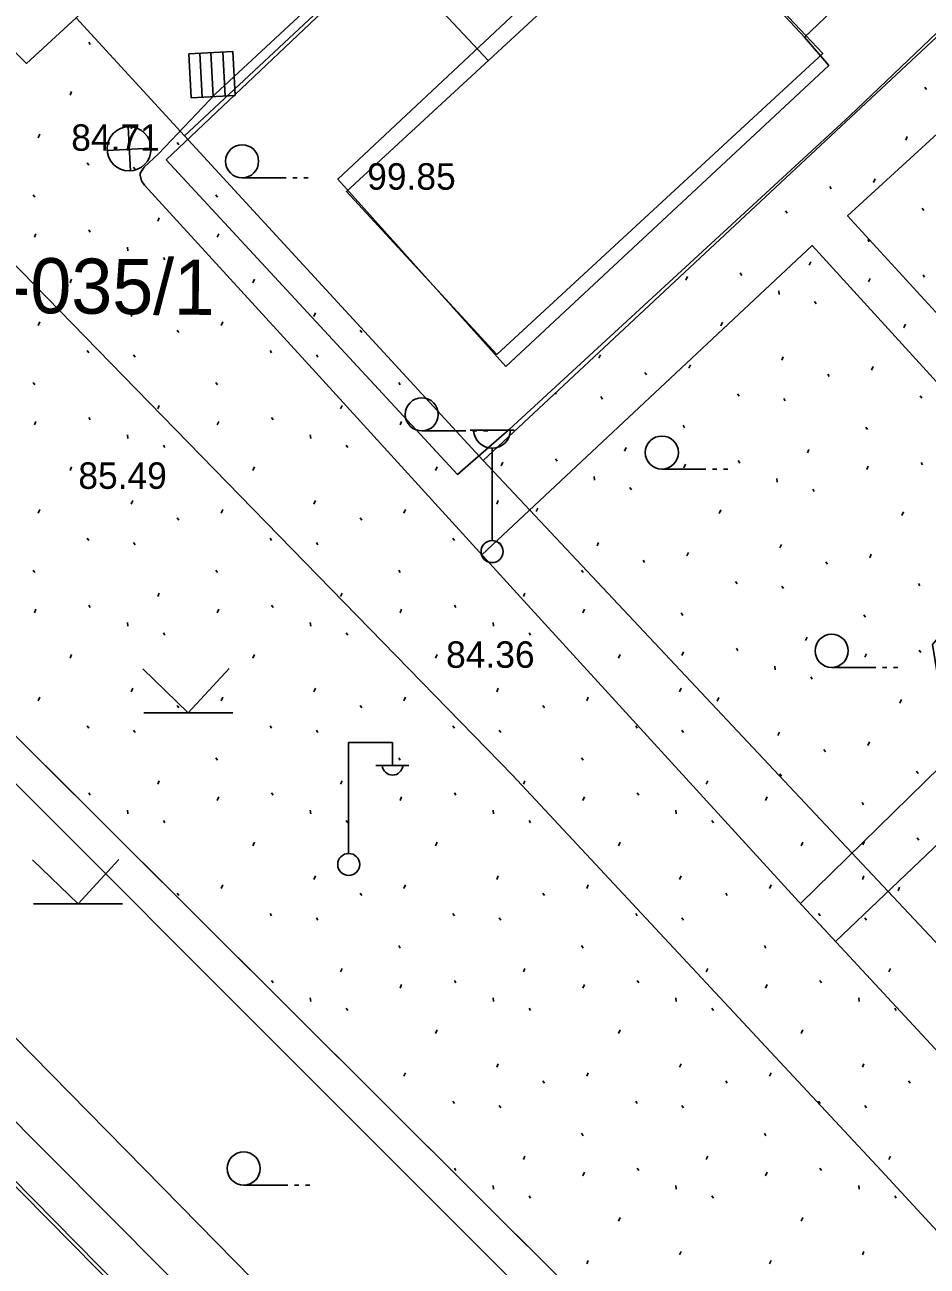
# Model space of a CAD drawing. Extents: x 412225 to 413380, y 4456471 to 4457189.
# Drawn here: x 412367.3 to 412408.2, y 4457046.4 to 4457102.7 of the extents above; entities that cross this region are included whole.
import ezdxf

# ---------------------------------------------------------------- set-up
doc = ezdxf.new("R2010")
doc.units = 0
for name, color, linetype in [('0_HALİHAZIR', 7, 'Continuous'), ('0_KADASTRO', 7, 'Continuous'), ('Level 27', 7, 'Continuous'), ('Level 41', 7, 'Continuous'), ('Level 56', 7, 'Continuous'), ('Level 57', 7, 'Continuous'), ('Level 59', 7, 'Continuous'), ('Level 62', 7, 'Continuous'), ('Level 8', 7, 'Continuous')]:
    doc.layers.add(name, color=color, linetype=linetype)

msp = doc.modelspace()

# ---------------------------------------------------------------- linework, layer by layer
at = {"layer": '0_HALİHAZIR'}
for p, q in [((412376.715, 4457101.483), (412374.717, 4457101.377)), ((412376.715, 4457101.483), (412374.717, 4457101.377)), ((412374.717, 4457101.377), (412374.823, 4457099.38)), ((412374.717, 4457101.377), (412374.823, 4457099.38)), ((412375.327, 4457099.406), (412375.221, 4457101.404)), ((412375.822, 4457099.433), (412375.716, 4457101.43)), ((412376.369, 4457099.461), (412376.263, 4457101.459)), ((412376.82, 4457099.485), (412376.715, 4457101.483)), ((412376.82, 4457099.485), (412376.715, 4457101.483)), ((412374.823, 4457099.38), (412376.82, 4457099.485)), ((412374.823, 4457099.38), (412376.82, 4457099.485)), ((412372.081, 4457096.06), (412371.976, 4457098.058)), ((412371.011, 4457096.995), (412373.008, 4457097.101)), ((412377.141, 4457095.752), (412379.141, 4457095.752)), ((412379.441, 4457095.752), (412379.641, 4457095.752)), ((412379.941, 4457095.752), (412380.141, 4457095.752)), ((412385.291, 4457084.277), (412387.291, 4457084.277)), ((412387.481, 4457084.305), (412389.481, 4457084.305)), ((412387.591, 4457084.277), (412387.791, 4457084.277)), ((412388.091, 4457084.277), (412388.291, 4457084.277)), ((412388.481, 4457079.305), (412388.481, 4457083.498)), ((412396.182, 4457082.545), (412398.182, 4457082.546)), ((412398.482, 4457082.546), (412398.682, 4457082.546)), ((412398.982, 4457082.546), (412399.182, 4457082.546)), ((412374.697, 4457071.497), (412372.637, 4457073.487)), ((412374.697, 4457071.497), (412376.547, 4457073.507)), ((412403.885, 4457073.554), (412405.886, 4457073.554)), ((412406.186, 4457073.554), (412406.386, 4457073.554)), ((412406.686, 4457073.554), (412406.886, 4457073.554)), ((412372.677, 4457071.497), (412376.717, 4457071.497)), ((412381.968, 4457065.141), (412381.968, 4457070.141)), ((412381.968, 4457070.141), (412383.968, 4457070.141)), ((412383.968, 4457069.141), (412383.968, 4457070.141)), ((412383.208, 4457069.101), (412384.708, 4457069.101)), ((412369.697, 4457062.837), (412367.637, 4457064.827)), ((412369.697, 4457062.837), (412371.547, 4457064.847)), ((412367.677, 4457062.837), (412371.717, 4457062.837)), ((412377.212, 4457050.082), (412379.212, 4457050.082)), ((412379.512, 4457050.082), (412379.712, 4457050.082)), ((412380.012, 4457050.082), (412380.212, 4457050.082))]:
    msp.add_line(p, q, dxfattribs=at)
for points in [[(412394.821, 4457110.525), (412409.529, 4457124.223), (412417.002, 4457115.773), (412402.655, 4457102.129)], [(412402.655, 4457102.129), (412403.755, 4457100.841), (412389.112, 4457087.201), (412381.481, 4457095.697), (412395.986, 4457109.277)]]:
    msp.add_lwpolyline(points, close=True, dxfattribs=at)
for points in [[(412301.706, 4457121.318), (412311.102, 4457113.16), (412330.158, 4457093.729), (412349.865, 4457074.031), (412372.694, 4457050.81), (412390.772, 4457032.428), (412419.372, 4457004.721)], [(412419.054, 4457119.278), (412422.523, 4457115.565), (412404.713, 4457098.559)], [(412417.329, 4457002.236), (412381.395, 4457038.35), (412347.738, 4457072.166), (412303.554, 4457116.902)], [(412389.287, 4457111.952), (412375.927, 4457099.56), (412373.349, 4457096.843), (412372.702, 4457096.237), (412372.515, 4457095.964), (412372.51, 4457095.866), (412372.583, 4457095.616), (412372.707, 4457095.413), (412380.486, 4457086.922), (412389.914, 4457076.573), (412402.552, 4457062.758), (412412.85, 4457051.661)], [(412389.252, 4457084.335), (412386.918, 4457082.293), (412373.701, 4457096.569), (412383.637, 4457105.991)], [(412422.853, 4457032.641), (412406.136, 4457050.742), (412389.41, 4457068.66), (412371.176, 4457087.358), (412353.875, 4457105.109)], [(412422.562, 4457081.66), (412420.42, 4457083.95), (412417.215, 4457085.435), (412414.747, 4457082.958), (412404.608, 4457094.022), (412415.788, 4457104.278), (412430.246, 4457088.829)], [(412404.713, 4457098.559), (412389.252, 4457084.335)], [(412388.011, 4457078.661), (412402.994, 4457092.677), (412413.829, 4457080.814), (412408.458, 4457074.592), (412408.84, 4457072.284), (412409.517, 4457069.739), (412402.475, 4457062.842)], [(412340.966, 4457076.102), (412361.717, 4457055.451), (412377.534, 4457039.414), (412399.513, 4457017.111), (412417.007, 4456999.535), (412433.199, 4456983.611)], [(412404.061, 4457061.132), (412413.306, 4457069.916), (412416.496, 4457066.513), (412422.083, 4457063.783), (412425.922, 4457067.072), (412434.752, 4457057.062), (412420.305, 4457043.492)]]:
    msp.add_lwpolyline(points, dxfattribs=at)
for centre, radius in [((412372.013, 4457097.066), 1), ((412377.141, 4457096.502), 0.75), ((412385.291, 4457085.027), 0.75), ((412396.182, 4457083.295), 0.75), ((412388.481, 4457078.805), 0.5), ((412403.885, 4457074.304), 0.75), ((412381.978, 4457064.617), 0.5), ((412377.212, 4457050.832), 0.75)]:
    msp.add_circle(centre, radius, dxfattribs=at)
for centre, radius, start, end in [((412388.481, 4457084.335), 0.837, 183.298, 356.9072), ((412383.968, 4457069.145), 0.474, 184.8384, 355.1464)]:
    msp.add_arc(centre, radius, start, end, dxfattribs=at)
at = {"layer": '0_KADASTRO'}
for points in [[(412531.386, 4456906.626), (412255.662, 4457181.172)], [(412369.613, 4457103.012), (412374.535, 4457097.659), (412388.074, 4457082.937), (412405.447, 4457099.156), (412423.162, 4457115.694)]]:
    msp.add_lwpolyline(points, dxfattribs=at)
msp.add_lwpolyline([(412374.535, 4457097.659), (412391.881, 4457113.852), (412409.622, 4457130.414), (412423.162, 4457115.694), (412405.447, 4457099.156), (412388.074, 4457082.937)], close=True, dxfattribs=at)
at = {"layer": 'Level 27'}
msp.add_line((412531.386, 4456906.626), (412255.662, 4457181.172), dxfattribs=at)
msp.add_lwpolyline([(412404.944, 4457135.499), (412377.179, 4457109.969), (412369.613, 4457103.012), (412374.535, 4457097.659), (412391.881, 4457113.852), (412409.622, 4457130.414)], dxfattribs=at)
at = {"layer": 'Level 41'}
for p, q in [((412370.184, 4457101.91), (412370.255, 4457101.803)), ((412369.335, 4457099.505), (412369.407, 4457099.665)), ((412408.118, 4457099.862), (412408.188, 4457099.755)), ((412372.107, 4457097.975), (412372.177, 4457098.135)), ((412367.897, 4457097.567), (412367.968, 4457097.727)), ((412374.202, 4457097.359), (412374.273, 4457097.253)), ((412407.244, 4457097.466), (412407.318, 4457097.626)), ((412370.117, 4457096.43), (412370.188, 4457096.323)), ((412372.216, 4457096.238), (412372.287, 4457096.131)), ((412405.787, 4457095.543), (412405.859, 4457095.702)), ((412403.797, 4457095.355), (412403.866, 4457095.249)), ((412367.661, 4457094.977), (412367.732, 4457094.87)), ((412375.954, 4457094.977), (412376.025, 4457094.87)), ((412401.799, 4457094.255), (412401.869, 4457094.147)), ((412407.995, 4457094.383), (412408.065, 4457094.276)), ((412373.313, 4457093.784), (412373.384, 4457093.943)), ((412367.719, 4457093.055), (412367.791, 4457093.215)), ((412370.184, 4457093.4), (412370.255, 4457093.293)), ((412376.012, 4457093.055), (412376.084, 4457093.215)), ((412378.542, 4457093.301), (412378.548, 4457093.293)), ((412405.524, 4457092.956), (412405.594, 4457092.848)), ((412371.942, 4457092.609), (412371.96, 4457092.449)), ((412373.572, 4457092.139), (412373.642, 4457092.032)), ((412402.871, 4457091.79), (412402.944, 4457091.948)), ((412397.27, 4457091.118), (412397.343, 4457091.277)), ((412399.738, 4457091.438), (412399.808, 4457091.33)), ((412405.562, 4457091.033), (412405.636, 4457091.192)), ((412408.031, 4457091.353), (412408.101, 4457091.245)), ((412369.335, 4457090.995), (412369.407, 4457091.155)), ((412377.628, 4457090.995), (412377.7, 4457091.155)), ((412401.488, 4457090.629), (412401.504, 4457090.469)), ((412403.113, 4457090.142), (412403.182, 4457090.034)), ((412372.107, 4457089.465), (412372.177, 4457089.625)), ((412380.4, 4457089.465), (412380.47, 4457089.625)), ((412367.897, 4457089.057), (412367.968, 4457089.217)), ((412376.19, 4457089.057), (412376.261, 4457089.217)), ((412398.865, 4457089.042), (412398.938, 4457089.201)), ((412407.157, 4457088.957), (412407.231, 4457089.116)), ((412374.202, 4457088.849), (412374.273, 4457088.743)), ((412382.495, 4457088.849), (412382.566, 4457088.743)), ((412370.117, 4457087.92), (412370.188, 4457087.813)), ((412378.41, 4457087.92), (412378.481, 4457087.813)), ((412372.216, 4457087.728), (412372.287, 4457087.621)), ((412380.509, 4457087.728), (412380.58, 4457087.621)), ((412393.328, 4457087.568), (412393.4, 4457087.727)), ((412397.407, 4457087.118), (412397.48, 4457087.278)), ((412401.621, 4457087.483), (412401.692, 4457087.643)), ((412395.417, 4457086.931), (412395.487, 4457086.824)), ((412403.709, 4457086.846), (412403.779, 4457086.739)), ((412405.699, 4457087.034), (412405.772, 4457087.193)), ((412367.661, 4457086.467), (412367.732, 4457086.36)), ((412375.954, 4457086.467), (412376.025, 4457086.36)), ((412384.247, 4457086.467), (412384.318, 4457086.36)), ((412391.353, 4457085.998), (412391.392, 4457085.936)), ((412393.419, 4457085.83), (412393.489, 4457085.722)), ((412399.615, 4457085.959), (412399.685, 4457085.851)), ((412401.712, 4457085.745), (412401.782, 4457085.638)), ((412407.908, 4457085.874), (412407.978, 4457085.766)), ((412373.313, 4457085.274), (412373.384, 4457085.433)), ((412381.606, 4457085.274), (412381.677, 4457085.433)), ((412367.719, 4457084.545), (412367.791, 4457084.705)), ((412370.184, 4457084.89), (412370.255, 4457084.783)), ((412376.012, 4457084.545), (412376.084, 4457084.705)), ((412378.477, 4457084.89), (412378.548, 4457084.783)), ((412384.305, 4457084.545), (412384.377, 4457084.705)), ((412397.144, 4457084.531), (412397.214, 4457084.423)), ((412405.437, 4457084.446), (412405.507, 4457084.338)), ((412371.942, 4457084.099), (412371.96, 4457083.939)), ((412380.235, 4457084.099), (412380.253, 4457083.939)), ((412373.572, 4457083.629), (412373.642, 4457083.522)), ((412381.865, 4457083.629), (412381.935, 4457083.522)), ((412394.491, 4457083.365), (412394.564, 4457083.523)), ((412402.784, 4457083.28), (412402.857, 4457083.438)), ((412388.89, 4457082.693), (412388.964, 4457082.853)), ((412391.359, 4457083.013), (412391.428, 4457082.905)), ((412397.183, 4457082.608), (412397.256, 4457082.768)), ((412399.651, 4457082.928), (412399.721, 4457082.82)), ((412407.944, 4457082.843), (412408.014, 4457082.736)), ((412369.335, 4457082.485), (412369.407, 4457082.645)), ((412377.628, 4457082.485), (412377.7, 4457082.645)), ((412385.921, 4457082.485), (412385.993, 4457082.645)), ((412393.108, 4457082.204), (412393.125, 4457082.044)), ((412405.475, 4457082.524), (412405.549, 4457082.683)), ((412394.733, 4457081.717), (412394.802, 4457081.61)), ((412401.401, 4457082.119), (412401.417, 4457081.959)), ((412403.026, 4457081.633), (412403.095, 4457081.525)), ((412372.107, 4457080.955), (412372.177, 4457081.115)), ((412380.4, 4457080.955), (412380.47, 4457081.115)), ((412388.693, 4457080.955), (412388.763, 4457081.115)), ((412367.897, 4457080.547), (412367.968, 4457080.707)), ((412376.19, 4457080.547), (412376.261, 4457080.707)), ((412384.483, 4457080.547), (412384.554, 4457080.707)), ((412390.485, 4457080.617), (412390.559, 4457080.776)), ((412398.778, 4457080.532), (412398.851, 4457080.691)), ((412407.07, 4457080.447), (412407.144, 4457080.606)), ((412374.202, 4457080.339), (412374.273, 4457080.233)), ((412382.495, 4457080.339), (412382.566, 4457080.233)), ((412370.117, 4457079.41), (412370.188, 4457079.303)), ((412378.41, 4457079.41), (412378.481, 4457079.303)), ((412386.703, 4457079.41), (412386.774, 4457079.303)), ((412372.216, 4457079.218), (412372.287, 4457079.111)), ((412380.509, 4457079.218), (412380.58, 4457079.111)), ((412388.802, 4457079.218), (412388.873, 4457079.111)), ((412393.241, 4457079.059), (412393.313, 4457079.218)), ((412401.534, 4457078.974), (412401.605, 4457079.133)), ((412395.33, 4457078.421), (412395.4, 4457078.314)), ((412397.32, 4457078.609), (412397.392, 4457078.768)), ((412403.622, 4457078.336), (412403.692, 4457078.23)), ((412405.612, 4457078.524), (412405.685, 4457078.683)), ((412367.661, 4457077.957), (412367.732, 4457077.85)), ((412375.954, 4457077.957), (412376.025, 4457077.85)), ((412384.247, 4457077.957), (412384.318, 4457077.85)), ((412392.54, 4457077.957), (412392.611, 4457077.85)), ((412399.528, 4457077.449), (412399.598, 4457077.341)), ((412401.625, 4457077.236), (412401.695, 4457077.128)), ((412407.821, 4457077.364), (412407.891, 4457077.257)), ((412373.313, 4457076.764), (412373.384, 4457076.923)), ((412381.606, 4457076.764), (412381.677, 4457076.923)), ((412389.899, 4457076.764), (412389.97, 4457076.923)), ((412367.719, 4457076.035), (412367.791, 4457076.195)), ((412370.184, 4457076.38), (412370.255, 4457076.273)), ((412376.012, 4457076.035), (412376.084, 4457076.195)), ((412378.477, 4457076.38), (412378.548, 4457076.273)), ((412384.305, 4457076.035), (412384.377, 4457076.195)), ((412386.77, 4457076.38), (412386.841, 4457076.273)), ((412392.598, 4457076.035), (412392.67, 4457076.195)), ((412397.057, 4457076.021), (412397.127, 4457075.914)), ((412371.942, 4457075.589), (412371.96, 4457075.429)), ((412380.235, 4457075.589), (412380.253, 4457075.429)), ((412388.528, 4457075.589), (412388.546, 4457075.429)), ((412405.35, 4457075.937), (412405.42, 4457075.829)), ((412373.572, 4457075.119), (412373.642, 4457075.012)), ((412381.865, 4457075.119), (412381.935, 4457075.012)), ((412390.158, 4457075.119), (412390.228, 4457075.012)), ((412402.697, 4457074.771), (412402.769, 4457074.929)), ((412399.564, 4457074.419), (412399.634, 4457074.311)), ((412407.857, 4457074.334), (412407.926, 4457074.226)), ((412369.335, 4457073.975), (412369.407, 4457074.135)), ((412377.628, 4457073.975), (412377.7, 4457074.135)), ((412385.921, 4457073.975), (412385.993, 4457074.135)), ((412394.214, 4457073.975), (412394.286, 4457074.135)), ((412397.096, 4457074.099), (412397.169, 4457074.258)), ((412405.388, 4457074.014), (412405.462, 4457074.173)), ((412401.314, 4457073.61), (412401.33, 4457073.45)), ((412372.107, 4457072.445), (412372.177, 4457072.605)), ((412380.4, 4457072.445), (412380.47, 4457072.605)), ((412388.693, 4457072.445), (412388.763, 4457072.605)), ((412396.986, 4457072.445), (412397.056, 4457072.605)), ((412402.939, 4457073.123), (412403.008, 4457073.015)), ((412367.897, 4457072.037), (412367.968, 4457072.197)), ((412376.19, 4457072.037), (412376.261, 4457072.197)), ((412384.483, 4457072.037), (412384.554, 4457072.197)), ((412392.776, 4457072.037), (412392.847, 4457072.197)), ((412398.69, 4457072.022), (412398.764, 4457072.182)), ((412406.983, 4457071.938), (412407.057, 4457072.097)), ((412374.202, 4457071.829), (412374.273, 4457071.723)), ((412382.495, 4457071.829), (412382.566, 4457071.723)), ((412390.788, 4457071.829), (412390.859, 4457071.723)), ((412370.117, 4457070.9), (412370.188, 4457070.793)), ((412378.41, 4457070.9), (412378.481, 4457070.793)), ((412386.703, 4457070.9), (412386.774, 4457070.793)), ((412394.996, 4457070.9), (412395.067, 4457070.793)), ((412372.216, 4457070.708), (412372.287, 4457070.601)), ((412380.509, 4457070.708), (412380.58, 4457070.601)), ((412388.802, 4457070.708), (412388.873, 4457070.601)), ((412397.095, 4457070.708), (412397.166, 4457070.601)), ((412401.447, 4457070.464), (412401.518, 4457070.623)), ((412403.535, 4457069.827), (412403.605, 4457069.72)), ((412405.525, 4457070.014), (412405.598, 4457070.174)), ((412375.954, 4457069.447), (412376.025, 4457069.34)), ((412384.247, 4457069.447), (412384.318, 4457069.34)), ((412392.54, 4457069.447), (412392.611, 4457069.34)), ((412401.538, 4457068.726), (412401.608, 4457068.618)), ((412407.734, 4457068.855), (412407.803, 4457068.747)), ((412373.313, 4457068.254), (412373.384, 4457068.413)), ((412381.606, 4457068.254), (412381.677, 4457068.413)), ((412389.899, 4457068.254), (412389.97, 4457068.413)), ((412398.192, 4457068.254), (412398.263, 4457068.413)), ((412370.184, 4457067.87), (412370.255, 4457067.763)), ((412376.012, 4457067.525), (412376.084, 4457067.685)), ((412378.477, 4457067.87), (412378.548, 4457067.763)), ((412384.305, 4457067.525), (412384.377, 4457067.685)), ((412386.77, 4457067.87), (412386.841, 4457067.763)), ((412392.598, 4457067.525), (412392.67, 4457067.685)), ((412395.063, 4457067.87), (412395.134, 4457067.763)), ((412400.891, 4457067.525), (412400.963, 4457067.685)), ((412371.942, 4457067.079), (412371.96, 4457066.919)), ((412380.235, 4457067.079), (412380.253, 4457066.919)), ((412388.528, 4457067.079), (412388.546, 4457066.919)), ((412396.821, 4457067.079), (412396.839, 4457066.919)), ((412405.263, 4457067.427), (412405.333, 4457067.319)), ((412373.572, 4457066.609), (412373.642, 4457066.502)), ((412381.865, 4457066.609), (412381.935, 4457066.502)), ((412390.158, 4457066.609), (412390.228, 4457066.502)), ((412398.451, 4457066.609), (412398.521, 4457066.502)), ((412377.628, 4457065.465), (412377.7, 4457065.625)), ((412385.921, 4457065.465), (412385.993, 4457065.625)), ((412394.214, 4457065.465), (412394.286, 4457065.625)), ((412402.507, 4457065.465), (412402.579, 4457065.625)), ((412405.301, 4457065.504), (412405.375, 4457065.664)), ((412407.769, 4457065.824), (412407.839, 4457065.717)), ((412376.19, 4457063.527), (412376.261, 4457063.687)), ((412380.4, 4457063.935), (412380.47, 4457064.095)), ((412384.483, 4457063.527), (412384.554, 4457063.687)), ((412388.693, 4457063.935), (412388.763, 4457064.095)), ((412392.776, 4457063.527), (412392.847, 4457063.687)), ((412396.986, 4457063.935), (412397.056, 4457064.095)), ((412401.069, 4457063.527), (412401.14, 4457063.687)), ((412405.279, 4457063.935), (412405.349, 4457064.095)), ((412406.896, 4457063.428), (412406.97, 4457063.587)), ((412374.202, 4457063.319), (412374.273, 4457063.213)), ((412382.495, 4457063.319), (412382.566, 4457063.213)), ((412390.788, 4457063.319), (412390.859, 4457063.213)), ((412399.081, 4457063.319), (412399.152, 4457063.213)), ((412378.41, 4457062.39), (412378.481, 4457062.283)), ((412380.509, 4457062.198), (412380.58, 4457062.091)), ((412386.703, 4457062.39), (412386.774, 4457062.283)), ((412388.802, 4457062.198), (412388.873, 4457062.091)), ((412394.996, 4457062.39), (412395.067, 4457062.283)), ((412397.095, 4457062.198), (412397.166, 4457062.091)), ((412403.289, 4457062.39), (412403.36, 4457062.283)), ((412405.388, 4457062.198), (412405.459, 4457062.091)), ((412384.247, 4457060.937), (412384.318, 4457060.83)), ((412392.54, 4457060.937), (412392.611, 4457060.83)), ((412400.833, 4457060.937), (412400.904, 4457060.83)), ((412381.606, 4457059.744), (412381.677, 4457059.903)), ((412389.899, 4457059.744), (412389.97, 4457059.903)), ((412398.192, 4457059.744), (412398.263, 4457059.903)), ((412406.485, 4457059.744), (412406.556, 4457059.903)), ((412378.477, 4457059.36), (412378.548, 4457059.253)), ((412384.305, 4457059.015), (412384.377, 4457059.175)), ((412386.77, 4457059.36), (412386.841, 4457059.253)), ((412392.598, 4457059.015), (412392.67, 4457059.175)), ((412395.063, 4457059.36), (412395.134, 4457059.253)), ((412400.891, 4457059.015), (412400.963, 4457059.175)), ((412403.356, 4457059.36), (412403.427, 4457059.253)), ((412380.235, 4457058.569), (412380.253, 4457058.409)), ((412388.528, 4457058.569), (412388.546, 4457058.409)), ((412396.821, 4457058.569), (412396.839, 4457058.409)), ((412405.114, 4457058.569), (412405.132, 4457058.409)), ((412381.865, 4457058.099), (412381.935, 4457057.992)), ((412390.158, 4457058.099), (412390.228, 4457057.992)), ((412398.451, 4457058.099), (412398.521, 4457057.992)), ((412406.744, 4457058.099), (412406.814, 4457057.992)), ((412385.921, 4457056.955), (412385.993, 4457057.115)), ((412394.214, 4457056.955), (412394.286, 4457057.115)), ((412402.507, 4457056.955), (412402.579, 4457057.115)), ((412384.483, 4457055.017), (412384.554, 4457055.177)), ((412388.693, 4457055.425), (412388.763, 4457055.585)), ((412392.776, 4457055.017), (412392.847, 4457055.177)), ((412396.986, 4457055.425), (412397.056, 4457055.585)), ((412401.069, 4457055.017), (412401.14, 4457055.177)), ((412405.279, 4457055.425), (412405.349, 4457055.585)), ((412390.788, 4457054.809), (412390.859, 4457054.703)), ((412399.081, 4457054.809), (412399.152, 4457054.703)), ((412407.374, 4457054.809), (412407.445, 4457054.703)), ((412386.703, 4457053.88), (412386.774, 4457053.773)), ((412388.802, 4457053.688), (412388.873, 4457053.581)), ((412394.996, 4457053.88), (412395.067, 4457053.773)), ((412397.095, 4457053.688), (412397.166, 4457053.581)), ((412403.289, 4457053.88), (412403.36, 4457053.773)), ((412405.388, 4457053.688), (412405.459, 4457053.581)), ((412392.54, 4457052.427), (412392.611, 4457052.32)), ((412400.833, 4457052.427), (412400.904, 4457052.32)), ((412389.899, 4457051.234), (412389.97, 4457051.393)), ((412398.192, 4457051.234), (412398.263, 4457051.393)), ((412406.485, 4457051.234), (412406.556, 4457051.393)), ((412386.77, 4457050.85), (412386.841, 4457050.743)), ((412392.598, 4457050.505), (412392.67, 4457050.665)), ((412395.063, 4457050.85), (412395.134, 4457050.743)), ((412400.891, 4457050.505), (412400.963, 4457050.665)), ((412403.356, 4457050.85), (412403.427, 4457050.743)), ((412388.528, 4457050.059), (412388.546, 4457049.899)), ((412390.158, 4457049.589), (412390.228, 4457049.482)), ((412396.821, 4457050.059), (412396.839, 4457049.899)), ((412398.451, 4457049.589), (412398.521, 4457049.482)), ((412405.114, 4457050.059), (412405.132, 4457049.899)), ((412406.744, 4457049.589), (412406.814, 4457049.482)), ((412394.214, 4457048.445), (412394.286, 4457048.605)), ((412402.507, 4457048.445), (412402.579, 4457048.605)), ((412396.986, 4457046.915), (412397.056, 4457047.075)), ((412405.279, 4457046.915), (412405.349, 4457047.075)), ((412392.776, 4457046.507), (412392.847, 4457046.667)), ((412401.069, 4457046.507), (412401.14, 4457046.667))]:
    msp.add_line(p, q, dxfattribs=at)
at = {"layer": 'Level 57'}
msp.add_line((412438.183, 4457029.626), (412388.074, 4457082.937), dxfattribs=at)
for points in [[(412315.011, 4457153.058), (412367.356, 4457100.937), (412369.613, 4457103.012)], [(412374.535, 4457097.659), (412388.074, 4457082.937), (412405.447, 4457099.156), (412423.162, 4457115.694)]]:
    msp.add_lwpolyline(points, dxfattribs=at)
at = {"layer": 'Level 59'}
msp.add_line((412388.307, 4457101.067), (412383.594, 4457106.116), dxfattribs=at)
msp.add_lwpolyline([(412388.7, 4457087.748), (412381.871, 4457095.13), (412396.579, 4457108.699), (412402.197, 4457102.751), (412403.485, 4457101.388)], close=True, dxfattribs=at)
at = {"layer": 'Level 62'}
msp.add_line((412267.88, 4457150.07), (412393.43, 4457023.16), dxfattribs=at)
at = {"layer": 'Level 8'}
msp.add_lwpolyline([(412706.1, 4457175.965), (412751.217, 4457041.463), (412764.575, 4457001.385), (412790.361, 4457003.87), (412821.118, 4456953.851), (412699.954, 4456860.338), (412631.485, 4456804.219), (412585.777, 4456849.927), (412523.439, 4456912.266), (412460.309, 4456974.831), (412403.512, 4457031.625), (412342.192, 4457092.946), (412287.774, 4457146.913), (412253.259, 4457181.199)], dxfattribs=at)

# ---------------------------------------------------------------- texts
at = {"layer": '0_HALİHAZIR'}
for s, p in [('84.71', (412369.39, 4457096.978)), ('99.85', (412382.816, 4457095.215)), ('85.49', (412369.712, 4457081.65)), ('84.36', (412386.395, 4457073.535))]:
    msp.add_text(s, height=1.2, dxfattribs=at).set_placement(p)
at = {"layer": 'Level 56'}
msp.add_text('01-1010-00-035/1', height=2.5, rotation=359.4136, dxfattribs=at).set_placement((412349.312, 4457089.805))

doc.saveas('drawing.dxf')
